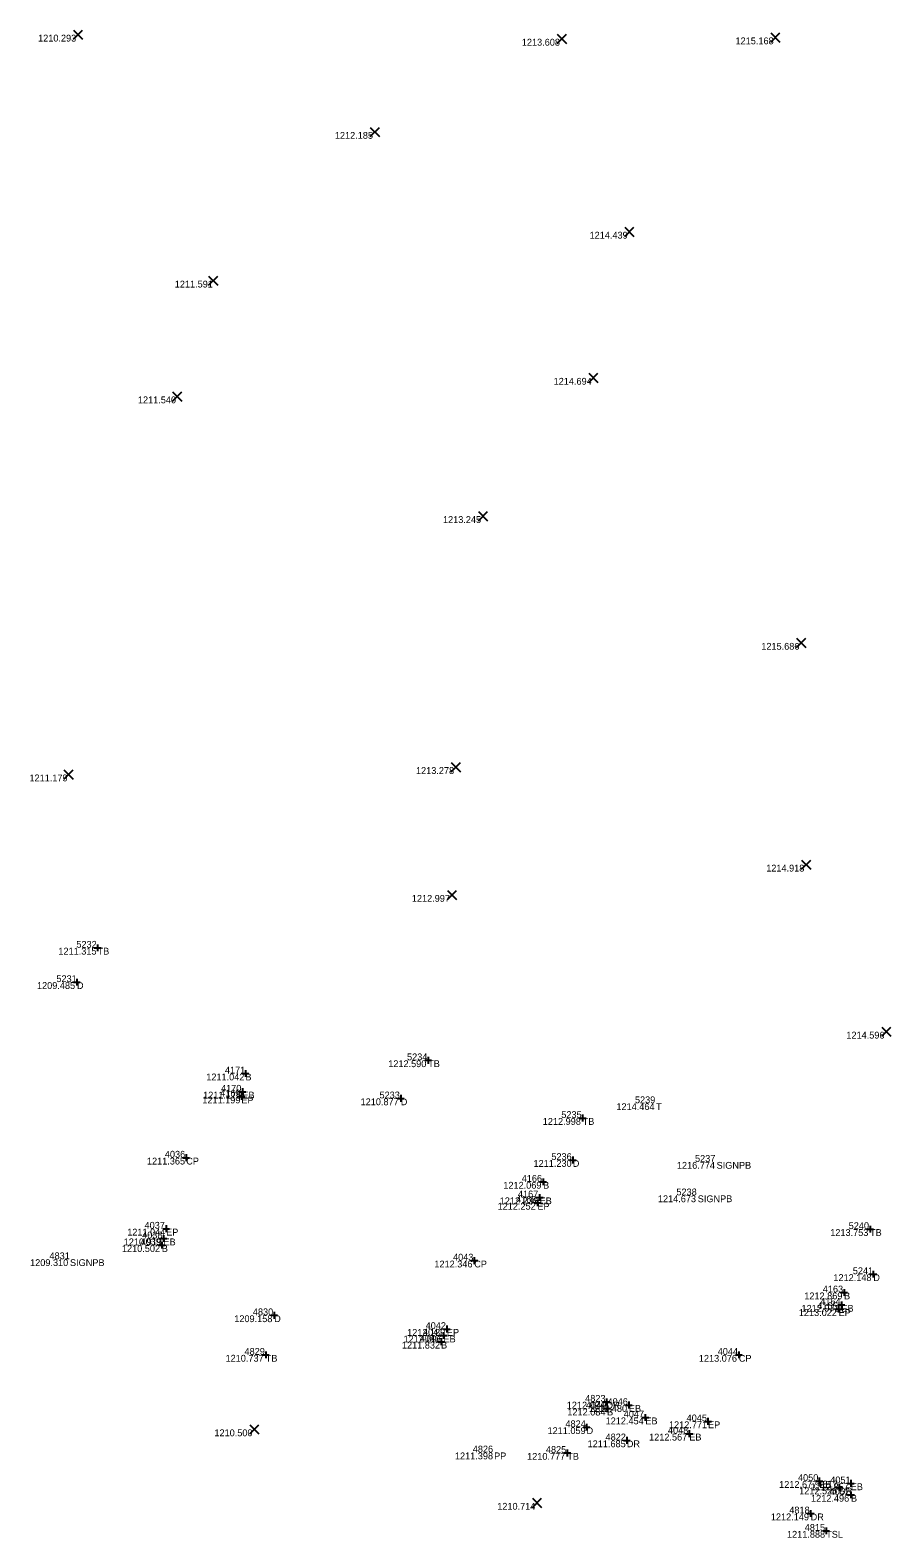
# Model space of a CAD drawing. Extents: x 2044997 to 2050342, y 455233 to 458054.
# Drawn here: x 2047864.8 to 2047990.7, y 456845.8 to 457066.6 of the extents above; entities that cross this region are included whole.
import ezdxf

# ---------------------------------------------------------------- set-up
doc = ezdxf.new("R2010")
doc.units = 0
for name, color, linetype in [('SV_X_Random_Point', 7, 'Continuous'), ('SV_X_Shot_Marker', 7, 'Continuous'), ('SV_X_Text_Comment', 7, 'Continuous'), ('SV_X_Text_Elevation', 7, 'Continuous'), ('SV_X_Text_Name', 7, 'Continuous')]:
    doc.layers.add(name, color=color, linetype=linetype)

msp = doc.modelspace()

# ---------------------------------------------------------------- linework, layer by layer
at = {"layer": 'SV_X_Random_Point'}
for p, q in [((2047871.11, 457065.28), (2047872.44, 457066.62)), ((2047871.11, 457066.62), (2047872.44, 457065.28)), ((2047941.91, 457064.68), (2047943.25, 457066.02)), ((2047941.91, 457066.02), (2047943.25, 457064.68)), ((2047973.18, 457064.88), (2047974.51, 457066.21)), ((2047973.18, 457066.21), (2047974.51, 457064.88)), ((2047914.56, 457051.04), (2047915.89, 457052.38)), ((2047914.56, 457052.38), (2047915.89, 457051.04)), ((2047951.8, 457036.42), (2047953.13, 457037.76)), ((2047951.8, 457037.76), (2047953.13, 457036.42)), ((2047890.89, 457029.27), (2047892.23, 457030.6)), ((2047890.89, 457030.6), (2047892.23, 457029.27)), ((2047946.53, 457015.04), (2047947.87, 457016.37)), ((2047946.53, 457016.37), (2047947.87, 457015.04)), ((2047885.63, 457012.31), (2047886.96, 457013.65)), ((2047885.63, 457013.65), (2047886.96, 457012.31)), ((2047930.38, 456994.79), (2047931.72, 456996.12)), ((2047930.38, 456996.12), (2047931.72, 456994.79)), ((2047976.95, 456976.22), (2047978.29, 456977.56)), ((2047976.95, 456977.56), (2047978.29, 456976.22)), ((2047869.74, 456956.95), (2047871.07, 456958.28)), ((2047869.74, 456958.28), (2047871.07, 456956.95)), ((2047926.42, 456958.03), (2047927.75, 456959.37)), ((2047926.42, 456959.37), (2047927.75, 456958.03)), ((2047977.67, 456943.74), (2047979.01, 456945.07)), ((2047977.67, 456945.07), (2047979.01, 456943.74)), ((2047925.86, 456939.31), (2047927.19, 456940.65)), ((2047925.86, 456940.65), (2047927.19, 456939.31)), ((2047989.4, 456919.29), (2047990.73, 456920.62)), ((2047989.4, 456920.62), (2047990.73, 456919.29)), ((2047896.93, 456861.06), (2047898.26, 456862.39)), ((2047896.93, 456862.39), (2047898.26, 456861.06)), ((2047938.28, 456850.3), (2047939.61, 456851.63)), ((2047938.28, 456851.63), (2047939.61, 456850.3))]:
    msp.add_line(p, q, dxfattribs=at)
at = {"layer": 'SV_X_Shot_Marker'}
for p, q in [((2047874.16, 456932.25), (2047875.16, 456932.25)), ((2047874.66, 456932.75), (2047874.66, 456931.75)), ((2047874.66, 456932.25), (2047874.66, 456932.25)), ((2047871.13, 456927.22), (2047872.13, 456927.22)), ((2047871.63, 456927.72), (2047871.63, 456926.72)), ((2047871.63, 456927.22), (2047871.63, 456927.22)), ((2047922.53, 456915.77), (2047923.53, 456915.77)), ((2047923.03, 456916.27), (2047923.03, 456915.27)), ((2047923.03, 456915.77), (2047923.03, 456915.77)), ((2047895.79, 456913.83), (2047896.79, 456913.83)), ((2047896.29, 456914.33), (2047896.29, 456913.33)), ((2047896.29, 456913.83), (2047896.29, 456913.83)), ((2047895.34, 456911.17), (2047896.34, 456911.17)), ((2047895.7, 456910.96), (2047895.7, 456909.96)), ((2047895.84, 456911.67), (2047895.84, 456910.67)), ((2047895.84, 456911.17), (2047895.84, 456911.17)), ((2047895.2, 456910.46), (2047896.2, 456910.46)), ((2047895.7, 456910.46), (2047895.7, 456910.46)), ((2047918.52, 456910.19), (2047919.52, 456910.19)), ((2047919.02, 456910.69), (2047919.02, 456909.69)), ((2047919.02, 456910.19), (2047919.02, 456910.19)), ((2047945.14, 456907.32), (2047946.14, 456907.32)), ((2047945.64, 456907.82), (2047945.64, 456906.82)), ((2047945.64, 456907.32), (2047945.64, 456907.32)), ((2047887.13, 456901.51), (2047888.13, 456901.51)), ((2047887.63, 456902.01), (2047887.63, 456901.01)), ((2047887.63, 456901.51), (2047887.63, 456901.51)), ((2047943.69, 456901.17), (2047944.69, 456901.17)), ((2047944.19, 456901.67), (2047944.19, 456900.67)), ((2047944.19, 456901.17), (2047944.19, 456901.17)), ((2047939.35, 456897.97), (2047940.35, 456897.97)), ((2047939.85, 456898.47), (2047939.85, 456897.47)), ((2047939.85, 456897.97), (2047939.85, 456897.97)), ((2047938.84, 456895.69), (2047939.84, 456895.69)), ((2047939.34, 456896.19), (2047939.34, 456895.19)), ((2047939.34, 456895.69), (2047939.34, 456895.69)), ((2047938.52, 456894.9), (2047939.52, 456894.9)), ((2047939.02, 456895.4), (2047939.02, 456894.4)), ((2047939.02, 456894.9), (2047939.02, 456894.9)), ((2047884.19, 456891.11), (2047885.19, 456891.11)), ((2047884.69, 456891.61), (2047884.69, 456890.61)), ((2047884.69, 456891.11), (2047884.69, 456891.11)), ((2047987.69, 456891.55), (2047987.69, 456890.55)), ((2047883.8, 456889.68), (2047884.8, 456889.68)), ((2047884.05, 456889.21), (2047884.05, 456888.21)), ((2047884.3, 456890.18), (2047884.3, 456889.18)), ((2047884.3, 456889.68), (2047884.3, 456889.68)), ((2047987.19, 456891.05), (2047988.19, 456891.05)), ((2047987.69, 456891.05), (2047987.69, 456891.05)), ((2047883.55, 456888.71), (2047884.55, 456888.71)), ((2047884.05, 456888.71), (2047884.05, 456888.71)), ((2047929.78, 456886.94), (2047929.78, 456885.94)), ((2047929.28, 456886.44), (2047930.28, 456886.44)), ((2047929.78, 456886.44), (2047929.78, 456886.44)), ((2047987.67, 456884.45), (2047988.67, 456884.45)), ((2047988.17, 456884.95), (2047988.17, 456883.95)), ((2047988.17, 456884.45), (2047988.17, 456884.45)), ((2047983.89, 456882.27), (2047983.89, 456881.27)), ((2047983.39, 456881.77), (2047984.39, 456881.77)), ((2047983.5, 456880.45), (2047983.5, 456879.45)), ((2047983.89, 456881.77), (2047983.89, 456881.77)), ((2047900, 456878.43), (2047901, 456878.43)), ((2047900.5, 456878.93), (2047900.5, 456877.93)), ((2047900.5, 456878.43), (2047900.5, 456878.43)), ((2047982.6, 456879.33), (2047983.6, 456879.33)), ((2047983, 456879.95), (2047984, 456879.95)), ((2047983.1, 456879.83), (2047983.1, 456878.83)), ((2047983.1, 456879.33), (2047983.1, 456879.33)), ((2047983.5, 456879.95), (2047983.5, 456879.95)), ((2047925.27, 456876.42), (2047926.27, 456876.42)), ((2047925.27, 456875.96), (2047925.27, 456874.96)), ((2047925.77, 456876.92), (2047925.77, 456875.92)), ((2047925.77, 456876.42), (2047925.77, 456876.42)), ((2047924.42, 456874.56), (2047925.42, 456874.56)), ((2047924.77, 456875.46), (2047925.77, 456875.46)), ((2047924.92, 456875.06), (2047924.92, 456874.06)), ((2047924.92, 456874.56), (2047924.92, 456874.56)), ((2047925.27, 456875.46), (2047925.27, 456875.46)), ((2047898.76, 456872.64), (2047899.76, 456872.64)), ((2047899.26, 456873.14), (2047899.26, 456872.14)), ((2047899.26, 456872.64), (2047899.26, 456872.64)), ((2047967.99, 456872.63), (2047968.99, 456872.63)), ((2047968.49, 456873.13), (2047968.49, 456872.13)), ((2047968.49, 456872.63), (2047968.49, 456872.63)), ((2047948.62, 456865.77), (2047949.62, 456865.77)), ((2047948.71, 456864.76), (2047949.71, 456864.76)), ((2047949.12, 456866.27), (2047949.12, 456865.27)), ((2047949.12, 456865.77), (2047949.12, 456865.77)), ((2047949.21, 456865.26), (2047949.21, 456864.26)), ((2047949.21, 456864.76), (2047949.21, 456864.76)), ((2047951.9, 456865.29), (2047952.9, 456865.29)), ((2047952.4, 456865.79), (2047952.4, 456864.79)), ((2047952.4, 456865.29), (2047952.4, 456865.29)), ((2047946.21, 456862.54), (2047946.21, 456861.54)), ((2047954.31, 456863.47), (2047955.31, 456863.47)), ((2047954.81, 456863.97), (2047954.81, 456862.97)), ((2047954.81, 456863.47), (2047954.81, 456863.47)), ((2047963.48, 456862.9), (2047964.48, 456862.9)), ((2047963.98, 456863.4), (2047963.98, 456862.4)), ((2047963.98, 456862.9), (2047963.98, 456862.9)), ((2047945.71, 456862.04), (2047946.71, 456862.04)), ((2047946.21, 456862.04), (2047946.21, 456862.04)), ((2047952.1, 456860.61), (2047952.1, 456859.61)), ((2047960.74, 456861.09), (2047961.74, 456861.09)), ((2047961.24, 456861.59), (2047961.24, 456860.59)), ((2047961.24, 456861.09), (2047961.24, 456861.09)), ((2047942.89, 456858.27), (2047943.89, 456858.27)), ((2047943.39, 456858.77), (2047943.39, 456857.77)), ((2047943.39, 456858.27), (2047943.39, 456858.27)), ((2047951.6, 456860.11), (2047952.6, 456860.11)), ((2047952.1, 456860.11), (2047952.1, 456860.11)), ((2047979.77, 456854.16), (2047980.77, 456854.16)), ((2047980.27, 456854.66), (2047980.27, 456853.66)), ((2047980.27, 456854.16), (2047980.27, 456854.16)), ((2047983.16, 456853.72), (2047983.16, 456852.72)), ((2047984.37, 456853.82), (2047985.37, 456853.82)), ((2047984.87, 456854.32), (2047984.87, 456853.32)), ((2047984.87, 456853.82), (2047984.87, 456853.82)), ((2047982.66, 456853.22), (2047983.66, 456853.22)), ((2047983.16, 456853.22), (2047983.16, 456853.22)), ((2047984.4, 456852.13), (2047985.4, 456852.13)), ((2047984.9, 456852.63), (2047984.9, 456851.63)), ((2047984.9, 456852.13), (2047984.9, 456852.13)), ((2047978.5, 456849.41), (2047979.5, 456849.41)), ((2047979, 456849.91), (2047979, 456848.91)), ((2047979, 456849.41), (2047979, 456849.41)), ((2047981.27, 456847.36), (2047981.27, 456846.36)), ((2047980.77, 456846.86), (2047981.77, 456846.86)), ((2047981.27, 456846.86), (2047981.27, 456846.86))]:
    msp.add_line(p, q, dxfattribs=at)

# ---------------------------------------------------------------- texts
at = {"layer": 'SV_X_Text_Comment'}
for s, p in [('TB', (2047874.66, 456931.25)), ('D', (2047871.63, 456926.22)), ('TB', (2047923.03, 456914.77)), ('B', (2047896.29, 456912.83)), ('EB', (2047895.84, 456910.17)), ('EP', (2047895.7, 456909.46)), ('D', (2047919.02, 456909.19)), ('T', (2047956.39, 456908.48)), ('TB', (2047945.64, 456906.32)), ('CP', (2047887.63, 456900.51)), ('D', (2047944.19, 456900.17)), ('SIGNPB', (2047965.24, 456899.89)), ('B', (2047939.85, 456896.97)), ('EB', (2047939.34, 456894.69)), ('SIGNPB', (2047962.48, 456894.99)), ('EP', (2047939.02, 456893.9)), ('EP', (2047884.69, 456890.11)), ('EB', (2047884.3, 456888.68)), ('TB', (2047987.69, 456890.05)), ('SIGNPB', (2047870.62, 456885.64)), ('B', (2047884.05, 456887.71)), ('CP', (2047929.78, 456885.44)), ('D', (2047988.17, 456883.45)), ('B', (2047983.89, 456880.77)), ('D', (2047900.5, 456877.43)), ('EP', (2047983.1, 456878.33)), ('EB', (2047983.5, 456878.95)), ('EP', (2047925.77, 456875.42)), ('B', (2047924.92, 456873.56)), ('EB', (2047925.27, 456874.46)), ('TB', (2047899.26, 456871.64)), ('CP', (2047968.49, 456871.63)), ('DR', (2047949.12, 456864.77)), ('B', (2047949.21, 456863.76)), ('EB', (2047952.4, 456864.29)), ('EB', (2047954.81, 456862.47)), ('EP', (2047963.98, 456861.9)), ('D', (2047946.21, 456861.04)), ('EB', (2047961.24, 456860.09)), ('PP', (2047932.68, 456857.34)), ('TB', (2047943.39, 456857.27)), ('DR', (2047952.1, 456859.11)), ('EB', (2047980.27, 456853.16)), ('EB', (2047984.87, 456852.82)), ('DR', (2047983.16, 456852.22)), ('B', (2047984.9, 456851.13)), ('DR', (2047979, 456848.41)), ('TSL', (2047981.27, 456845.86))]:
    msp.add_text(s, height=1, dxfattribs=at).set_placement(p)
at = {"layer": 'SV_X_Text_Elevation'}
for s, p in [('1210.293', (2047865.95, 457064.95)), ('1215.168', (2047968.01, 457064.55)), ('1213.608', (2047936.74, 457064.35)), ('1212.185', (2047909.38, 457050.71)), ('1214.439', (2047946.65, 457036.09)), ('1211.591', (2047885.95, 457028.93)), ('1214.694', (2047941.39, 457014.7)), ('1211.540', (2047880.56, 457011.98)), ('1213.245', (2047925.2, 456994.45)), ('1215.686', (2047971.78, 456975.89)), ('1211.179', (2047864.69, 456956.62)), ('1213.278', (2047921.25, 456957.7)), ('1214.918', (2047972.5, 456943.41)), ('1212.997', (2047920.64, 456938.98)), ('1211.315', (2047868.92, 456931.25)), ('1209.485', (2047865.79, 456926.22)), ('1214.596', (2047984.23, 456918.95)), ('1212.590', (2047917.19, 456914.77)), ('1211.042', (2047890.56, 456912.83)), ('1211.175', (2047890.1, 456910.17)), ('1211.199', (2047889.98, 456909.46)), ('1210.877', (2047913.14, 456909.19)), ('1214.464', (2047950.58, 456908.48)), ('1212.998', (2047939.8, 456906.32)), ('1211.365', (2047881.88, 456900.51)), ('1211.230', (2047938.45, 456900.17)), ('1216.774', (2047959.43, 456899.89)), ('1212.069', (2047934.03, 456896.97)), ('1212.236', (2047933.5, 456894.69)), ('1214.673', (2047956.65, 456894.99)), ('1212.252', (2047933.19, 456893.9)), ('1211.044', (2047878.99, 456890.11)), ('1210.919', (2047878.48, 456888.68)), ('1213.753', (2047981.87, 456890.05)), ('1209.310', (2047864.78, 456885.64)), ('1210.502', (2047878.22, 456887.71)), ('1212.346', (2047923.94, 456885.44)), ('1212.148', (2047982.33, 456883.45)), ('1212.869', (2047978.07, 456880.77)), ('1209.158', (2047894.66, 456877.43)), ('1213.022', (2047977.27, 456878.33)), ('1212.972', (2047977.66, 456878.95)), ('1212.189', (2047919.95, 456875.42)), ('1211.832', (2047919.19, 456873.56)), ('1212.096', (2047919.43, 456874.46)), ('1210.737', (2047893.38, 456871.64)), ('1213.076', (2047962.64, 456871.63)), ('1212.024', (2047943.31, 456864.77)), ('1212.084', (2047943.4, 456863.76)), ('1212.480', (2047946.56, 456864.29)), ('1212.454', (2047949, 456862.47)), ('1212.771', (2047958.27, 456861.9)), ('1210.500', (2047891.75, 456860.72)), ('1211.059', (2047940.5, 456861.04)), ('1212.567', (2047955.36, 456860.09)), ('1211.398', (2047926.95, 456857.34)), ('1210.777', (2047937.51, 456857.27)), ('1211.685', (2047946.36, 456859.11)), ('1212.677', (2047974.39, 456853.16)), ('1212.857', (2047978.99, 456852.82)), ('1212.526', (2047977.32, 456852.22)), ('1212.496', (2047979.06, 456851.13)), ('1210.714', (2047933.14, 456849.96)), ('1212.149', (2047973.18, 456848.41)), ('1211.888', (2047975.54, 456845.86))]:
    msp.add_text(s, height=1, dxfattribs=at).set_placement(p)
at = {"layer": 'SV_X_Text_Name'}
for s, p in [('5232', (2047871.55, 456932.25)), ('5231', (2047868.63, 456927.22)), ('5234', (2047919.94, 456915.77)), ('4171', (2047893.29, 456913.83)), ('4169', (2047892.6, 456910.46)), ('4170', (2047892.72, 456911.17)), ('5233', (2047915.91, 456910.19)), ('5239', (2047953.29, 456909.48)), ('5235', (2047942.51, 456907.32)), ('4036', (2047884.5, 456901.51)), ('5236', (2047941.06, 456901.17)), ('5237', (2047962.08, 456900.89)), ('4166', (2047936.72, 456897.97)), ('4168', (2047935.9, 456894.9)), ('4167', (2047936.17, 456895.69)), ('5238', (2047959.36, 456895.99)), ('4037', (2047881.53, 456891.11)), ('5240', (2047984.57, 456891.05)), ('4039', (2047880.95, 456888.71)), ('4038', (2047881.18, 456889.68)), ('4831', (2047867.62, 456886.64)), ('4043', (2047926.67, 456886.44)), ('5241', (2047985.17, 456884.45)), ('4163', (2047980.78, 456881.77)), ('4165', (2047979.97, 456879.33)), ('4164', (2047980.41, 456879.95)), ('4830', (2047897.38, 456878.43)), ('4041', (2047922.27, 456875.46)), ('4042', (2047922.66, 456876.42)), ('4829', (2047896.16, 456872.64)), ('4040', (2047921.8, 456874.56)), ('4044', (2047965.4, 456872.63)), ('4823', (2047946.01, 456865.77)), ('4049', (2047946.11, 456864.76)), ('4046', (2047949.28, 456865.29)), ('4824', (2047943.12, 456862.04)), ('4047', (2047951.65, 456863.47)), ('4045', (2047960.85, 456862.9)), ('4822', (2047948.99, 456860.11)), ('4048', (2047958.12, 456861.09)), ('4826', (2047929.56, 456858.34)), ('4825', (2047940.26, 456858.27)), ('4050', (2047977.15, 456854.16)), ('4817', (2047979.99, 456853.22)), ('4051', (2047981.87, 456853.82)), ('4052', (2047981.78, 456852.13)), ('4818', (2047975.88, 456849.41)), ('4815', (2047978.14, 456846.86))]:
    msp.add_text(s, height=1, dxfattribs=at).set_placement(p)

doc.saveas('drawing.dxf')
